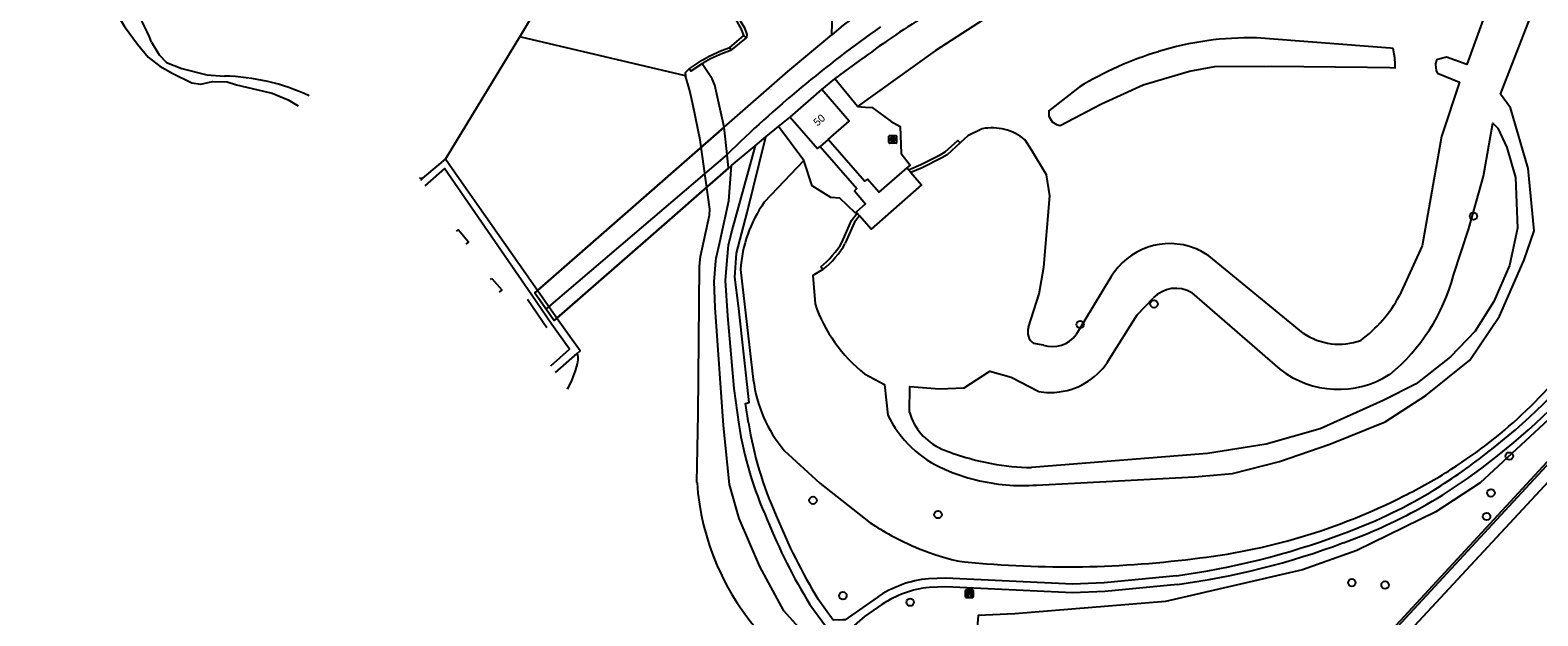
# Model space of a CAD drawing. Extents: x 155640 to 156810, y 382822 to 384046.
# Drawn here: x 156042.4 to 156240.5, y 383326 to 383402.9 of the extents above; entities that cross this region are included whole.
import ezdxf

# ---------------------------------------------------------------- set-up
doc = ezdxf.new("R2010")
doc.units = 0
for name, color, linetype in [('IMGEO_Bank', 7, 'Continuous'), ('IMGEO_Boom', 7, 'Continuous'), ('IMGEO_Dek', 7, 'Continuous'), ('IMGEO_Fietspad_gesloten', 7, 'Continuous'), ('IMGEO_Gemaal', 7, 'Continuous'), ('IMGEO_Groenvoorziening', 7, 'Continuous'), ('IMGEO_Haag', 7, 'Continuous'), ('IMGEO_Hek', 7, 'Continuous'), ('IMGEO_Kademuur', 7, 'Continuous'), ('IMGEO_Lijnafwatering', 7, 'Continuous'), ('IMGEO_Loofbos', 7, 'Continuous'), ('IMGEO_Meer_plas_ven_vijver', 7, 'Continuous'), ('IMGEO_Muur', 7, 'Continuous'), ('IMGEO_Pand', 7, 'Continuous'), ('IMGEO_Pand_nummerreeks', 7, 'Continuous'), ('IMGEO_Rijbaan_lokaal_gesloten', 7, 'Continuous'), ('IMGEO_Rioolput', 7, 'Continuous'), ('IMGEO_Terreindeel_halfverhard', 7, 'Continuous'), ('IMGEO_Voetpad_gesloten', 7, 'Continuous'), ('IMGEO_Voetpad_halfverhard', 7, 'Continuous'), ('IMGEO_Waterloop', 7, 'Continuous')]:
    doc.layers.add(name, color=color, linetype=linetype)

msp = doc.modelspace()

# ---------------------------------------------------------------- linework, layer by layer
at = {"layer": 'IMGEO_Bank'}
for p, q in [((156165.29, 383328.46), (156165.29, 383329.3)), ((156165.29, 383329.3), (156165.29, 383328.46)), ((156165.36, 383329.39), (156166.21, 383329.39)), ((156166.21, 383329.39), (156165.36, 383329.39)), ((156166.22, 383328.39), (156165.37, 383328.39)), ((156165.37, 383328.39), (156166.22, 383328.39)), ((156165.99, 383328.79), (156165.59, 383328.79)), ((156165.6, 383328.89), (156165.6, 383329)), ((156165.64, 383329), (156165.64, 383328.89)), ((156165.93, 383329.01), (156165.65, 383329.01)), ((156165.65, 383328.89), (156165.93, 383328.89)), ((156165.94, 383328.89), (156165.94, 383329)), ((156165.98, 383329), (156165.98, 383328.89)), ((156166.29, 383329.31), (156166.29, 383328.47)), ((156166.29, 383328.47), (156166.29, 383329.31))]:
    msp.add_line(p, q, dxfattribs=at)
for points in [[(156165.54, 383328.79), (156165.39, 383328.79), (156165.51, 383328.89), (156165.59, 383328.89)], [(156165.59, 383329.01), (156165.51, 383329.01), (156165.51, 383329.17), (156166.07, 383329.17), (156166.07, 383329.01), (156165.99, 383329.01)], [(156165.59, 383328.78), (156165.59, 383328.57), (156165.54, 383328.57), (156165.54, 383328.78)], [(156165.99, 383328.89), (156166.07, 383328.89), (156166.18, 383328.79), (156166.04, 383328.79)], [(156166.04, 383328.78), (156166.04, 383328.57), (156165.99, 383328.57), (156165.99, 383328.78)]]:
    msp.add_lwpolyline(points, dxfattribs=at)
for centre, radius, start, end in [((156165.37, 383329.31), 0.0779, 92.4484, 184.2845), ((156165.37, 383329.31), 0.0779, 92.4484, 184.2845), ((156165.37, 383328.47), 0.0779, 182.4484, 274.2845), ((156165.37, 383328.47), 0.0779, 182.4484, 274.2845), ((156165.54, 383328.78), 0.00671, 2.8957, 87.1043), ((156165.59, 383329), 0.00671, 2.8957, 87.1043), ((156165.59, 383328.89), 0.00671, 272.8957, 357.1043), ((156165.59, 383328.78), 0.00671, 92.8957, 177.1043), ((156165.65, 383329), 0.00671, 92.8957, 177.1043), ((156165.65, 383328.89), 0.00671, 182.8957, 267.1043), ((156165.93, 383329), 0.00671, 2.8957, 87.1043), ((156165.93, 383328.89), 0.00671, 272.8957, 357.1043), ((156165.99, 383329), 0.00671, 92.8957, 177.1043), ((156165.99, 383328.89), 0.00671, 182.8957, 267.1043), ((156165.99, 383328.78), 0.00671, 2.8957, 87.1043), ((156166.04, 383328.78), 0.00671, 92.8957, 177.1043), ((156166.21, 383329.31), 0.0779, 2.4484, 94.2845), ((156166.21, 383329.31), 0.0779, 2.4484, 94.2845), ((156166.21, 383328.47), 0.0779, 272.4484, 4.2845), ((156166.21, 383328.47), 0.0779, 272.4484, 4.2845)]:
    msp.add_arc(centre, radius, start, end, dxfattribs=at)
at = {"layer": 'IMGEO_Boom'}
for centre in [(156232.01, 383378.46), (156190.05, 383366.93), (156180.35, 383364.23), (156236.72, 383346.96), (156145.25, 383341.15), (156234.31, 383342.12), (156161.67, 383339.28), (156233.74, 383339.02), (156216.04, 383330.34), (156220.4, 383330.03), (156149.18, 383328.63), (156158.02, 383327.77)]:
    msp.add_circle(centre, 0.489, dxfattribs=at)
at = {"layer": 'IMGEO_Dek'}
msp.add_lwpolyline([(156134.16, 383384.76), (156133.97, 383386.57), (156133.6, 383390.13), (156118.82, 383377.21), (156109.06, 383368.68), (156108.72, 383368.39), (156111.25, 383364.74), (156123.58, 383375.52)], close=True, dxfattribs=at)
at = {"layer": 'IMGEO_Fietspad_gesloten'}
for points in [[(156150.23, 383404.29), (156149.2, 383403.52), (156147.71, 383402.28)], [(156133.6, 383390.13), (156141.94, 383397.47), (156147.71, 383402.28)], [(156133.97, 383386.57), (156133.6, 383390.13), (156118.82, 383377.21), (156109.06, 383368.68), (156108.72, 383368.39), (156110.18, 383366.29)], [(156133.97, 383386.57), (156133.6, 383390.13)], [(156133.97, 383386.57), (156110.18, 383366.29)]]:
    msp.add_lwpolyline(points, dxfattribs=at)
msp.add_arc((156250.07, 383267.46), 166.33, 125.2347, 134.2683, dxfattribs=at)
at = {"layer": 'IMGEO_Gemaal'}
for points in [[(156146.17, 383387.61), (156151, 383382.09), (156150.68, 383381.79), (156152.14, 383380.07), (156150.93, 383378.99)], [(156157.57, 383384.79), (156153.89, 383381.6), (156152.39, 383383.33), (156152.03, 383383.04), (156147.24, 383388.53)], [(156158.1, 383384.19), (156159.51, 383382.59), (156152.89, 383376.75), (156151.37, 383378.49)], [(156157.79, 383384.54), (156157.57, 383384.79)], [(156150.93, 383378.99), (156151.07, 383378.83)]]:
    msp.add_lwpolyline(points, dxfattribs=at)
at = {"layer": 'IMGEO_Groenvoorziening'}
for points in [[(156220.21, 383413.56), (156208.37, 383415.13), (156193.51, 383414.01), (156185.08, 383411.88), (156169.11, 383405.2), (156161.31, 383400.14), (156151.11, 383392.84)], [(156049.38, 383411.45), (156049.77, 383410.94), (156050.89, 383409.54), (156052.4, 383407.41), (156054.82, 383403.34), (156056.52, 383401.03), (156057.89, 383399.33), (156059.44, 383398.17), (156061.14, 383397.18), (156063.64, 383395.96), (156064.83, 383395.8), (156066.37, 383396.14), (156068.27, 383396.1), (156069.52, 383395.72), (156072.3, 383395.04), (156074.18, 383394.59), (156076.3, 383393.73), (156077.61, 383392.95)], [(156133.6, 383390.13), (156132.36, 383395.64), (156132, 383396.49), (156130.78, 383398.32), (156130.72, 383398.49)], [(156151.11, 383392.84), (156148.1, 383396.47)], [(156144.04, 383385.78), (156140.7, 383390.21)], [(156144.04, 383385.78), (156138.85, 383380.29)], [(156158.97, 383299.53), (156158.12, 383305.72), (156154.76, 383312), (156145.77, 383321.85), (156141.4, 383326.64), (156138.25, 383332.47), (156135.54, 383338.76), (156134.29, 383343.24), (156133.47, 383350.98), (156132.4, 383366.47), (156132.25, 383369.83), (156132.5, 383372.59), (156132.53, 383372.94), (156133, 383375.06), (156134.21, 383380.49), (156134.56, 383385.1)], [(156135.73, 383371.45), (156137.41, 383357.01)], [(156247.6, 383349.79), (156224.23, 383324.63)], [(156141.46, 383347.7), (156146.14, 383343.41), (156152.77, 383338.21)]]:
    msp.add_lwpolyline(points, dxfattribs=at)
for centre, radius, start, end in [((156153.04, 383370.31), 17.35, 144.9075, 176.2504), ((156194.92, 383399.02), 63.73, 302.4386, 325.059), ((156155.07, 383359.16), 17.79, 186.943, 220.0843), ((156195.43, 383397.91), 62.52, 296.0194, 302.5827), ((156186.49, 383413.22), 80.21, 276.1958, 296.9624), ((156172.46, 383367.49), 35.28, 236.083, 246.483), ((156172.49, 383367.56), 35.35, 246.4901, 256.3906), ((156178.48, 383464.15), 131.73, 263.7643, 277.2713)]:
    msp.add_arc(centre, radius, start, end, dxfattribs=at)
at = {"layer": 'IMGEO_Haag'}
for points in [[(156221.5, 383323.96), (156251.39, 383356.23)], [(156248.62, 383353.69), (156221.29, 383324.16), (156221.5, 383323.96)]]:
    msp.add_lwpolyline(points, dxfattribs=at)
at = {"layer": 'IMGEO_Hek'}
for points in [[(156118.82, 383377.21), (156133.6, 383390.13)], [(156134.16, 383384.76), (156123.58, 383375.52)], [(156109.06, 383368.68), (156118.82, 383377.21)], [(156123.58, 383375.52), (156111.25, 383364.74)], [(156108.72, 383368.39), (156109.06, 383368.68)], [(156224.23, 383324.63), (156247.6, 383349.79)]]:
    msp.add_lwpolyline(points, dxfattribs=at)
at = {"layer": 'IMGEO_Kademuur'}
for points in [[(156136.18, 383402.16), (156135.87, 383403), (156135.09, 383404.3), (156134.45, 383405.04), (156133.74, 383405.8), (156132.68, 383406.67), (156131.65, 383407.53), (156130.44, 383408.47), (156129.17, 383409.25), (156127.67, 383409.91), (156125.97, 383410.51), (156124.86, 383411.06), (156123.68, 383411.64), (156122.76, 383412.09), (156121.69, 383412.85)], [(156134.05, 383406.06), (156134.74, 383405.31), (156135.41, 383404.53), (156136.23, 383403.17), (156136.55, 383402.3), (156136.52, 383401.86)], [(156129, 383397.82), (156130.67, 383398.93), (156131.59, 383399.48), (156133.23, 383400.19), (156134.32, 383400.59)], [(156134.46, 383400.22), (156133.38, 383399.81), (156131.77, 383399.12), (156130.88, 383398.6), (156130.72, 383398.49)], [(156130.72, 383398.49), (156129.22, 383397.48), (156129, 383397.82)]]:
    msp.add_lwpolyline(points, dxfattribs=at)
at = {"layer": 'IMGEO_Lijnafwatering'}
msp.add_lwpolyline([(156107.73, 383367.54), (156110.27, 383363.84)], dxfattribs=at)
at = {"layer": 'IMGEO_Loofbos'}
msp.add_lwpolyline([(156247.72, 383357.2), (156232.9, 383343.44), (156227.05, 383339.62), (156216.67, 383334.58), (156209.55, 383332.04), (156191.54, 383327.89), (156171.75, 383326.24), (156166.93, 383326.02), (156165.8, 383312.12), (156170.26, 383297.35), (156172.98, 383289.47), (156173.05, 383289.27), (156175.83, 383284.03), (156175.34, 383282.18), (156181.24, 383276.16), (156184.1, 383272.27), (156188.18, 383271.12), (156190.33, 383268.72), (156196.74, 383263.77), (156194.3, 383261.15), (156197.14, 383258.02), (156201.28, 383254.76), (156204.42, 383253.88), (156208.17, 383256.03)], dxfattribs=at)
at = {"layer": 'IMGEO_Meer_plas_ven_vijver'}
for points in [[(156106.72, 383402.02), (156114.8, 383415.47)], [(156058.34, 383401.31), (156059.37, 383399.63), (156060.31, 383398.65), (156062.32, 383397.83), (156065.63, 383397.01), (156067.93, 383396.84)], [(156096.95, 383385.92), (156106.72, 383402.02)], [(156128.5, 383396.88), (156106.72, 383402.02)], [(156129, 383397.82), (156128.74, 383397.55), (156128.46, 383397.26), (156128.5, 383396.88)], [(156130.01, 383343.5), (156130.18, 383352.47), (156130.34, 383371.89), (156130.46, 383373.16), (156131.67, 383378.6), (156131.71, 383379.38), (156130.42, 383388.48), (156129.5, 383392.94), (156129.07, 383394.91), (156128.5, 383396.88)], [(156093.54, 383383.47), (156094.01, 383383.43)], [(156114.26, 383360.43), (156114.35, 383360.04), (156114.34, 383359.6), (156114.26, 383359.07), (156114.02, 383358.14), (156113.48, 383356.73), (156112.96, 383355.73)]]:
    msp.add_lwpolyline(points, dxfattribs=at)
for centre, radius, start, end in [((156030.75, 383390.28), 29.72, 21.7875, 66.9009), ((156067.31, 383368.96), 27.89, 65.0916, 88.7313), ((156162.9, 383345.69), 32.96, 183.8144, 223.1671)]:
    msp.add_arc(centre, radius, start, end, dxfattribs=at)
at = {"layer": 'IMGEO_Muur'}
for points in [[(156134.32, 383400.59), (156136.18, 383402.16)], [(156134.46, 383400.22), (156136.52, 383401.86)], [(156136.52, 383401.86), (156136.18, 383402.16)], [(156134.32, 383400.59), (156134.46, 383400.22)], [(156157.79, 383384.54), (156159.42, 383385.23), (156161.95, 383386.49), (156162.59, 383386.89), (156164.26, 383388.41), (156164.57, 383388.08)], [(156164.57, 383388.08), (156162.86, 383386.53), (156162.17, 383386.1), (156159.61, 383384.82), (156158.1, 383384.19)], [(156094.01, 383383.43), (156096.16, 383385.25), (156096.95, 383385.92)], [(156114.26, 383360.43), (156114.67, 383360.78), (156113.3, 383362.68), (156111.75, 383364.82), (156109.06, 383368.68), (156097.84, 383384.66), (156096.95, 383385.92)], [(156093.73, 383383.19), (156094.01, 383383.43)], [(156110.81, 383358.79), (156113.28, 383360.98), (156110.93, 383364.25), (156108.33, 383368.1), (156096.82, 383384.7), (156094.25, 383382.46)], [(156158.1, 383384.19), (156157.79, 383384.54)], [(156149.07, 383375.1), (156150.31, 383377.88), (156151.07, 383378.83)], [(156151.37, 383378.49), (156150.7, 383377.65), (156149.48, 383374.9)], [(156151.07, 383378.83), (156151.37, 383378.49)], [(156146.54, 383371.46), (156146.26, 383371.81)], [(156111.41, 383357.93), (156114.26, 383360.43)]]:
    msp.add_lwpolyline(points, dxfattribs=at)
for centre, radius, start, end in [((156139.2, 383380.7), 11.36, 308.4635, 330.4373), ((156139.23, 383380.67), 11.77, 308.4256, 330.5808)]:
    msp.add_arc(centre, radius, start, end, dxfattribs=at)
at = {"layer": 'IMGEO_Pand'}
for points in [[(156142.25, 383391.47), (156146.42, 383395.08)], [(156147.24, 383388.53), (156150.02, 383390.93), (156146.42, 383395.08)], [(156142.25, 383391.47), (156145.85, 383387.33), (156146.17, 383387.61)], [(156147.24, 383388.53), (156146.17, 383387.61)]]:
    msp.add_lwpolyline(points, dxfattribs=at)
at = {"layer": 'IMGEO_Rijbaan_lokaal_gesloten'}
for points in [[(156098.43, 383376.48), (156098.67, 383376.67), (156099.98, 383375.08), (156099.62, 383374.78)], [(156102.88, 383370.12), (156103.05, 383370.26)], [(156103.05, 383370.26), (156104.35, 383368.77), (156104.02, 383368.49)]]:
    msp.add_lwpolyline(points, dxfattribs=at)
at = {"layer": 'IMGEO_Rioolput'}
for p, q in [((156155.23, 383388.11), (156155.23, 383388.96)), ((156155.31, 383389.03), (156156.16, 383389.03)), ((156156.16, 383388.03), (156155.31, 383388.03)), ((156155.72, 383388.81), (156155.75, 383388.81)), ((156155.74, 383388.25), (156155.72, 383388.25)), ((156156.24, 383388.96), (156156.24, 383388.11))]:
    msp.add_line(p, q, dxfattribs=at)
for points in [[(156155.23, 383388.11), (156155.23, 383388.96)], [(156155.31, 383389.03), (156156.16, 383389.03)], [(156156.16, 383388.03), (156155.31, 383388.03)], [(156155.82, 383388.73), (156155.57, 383388.73), (156155.57, 383388.33)], [(156155.57, 383388.33), (156155.7, 383388.33), (156155.7, 383388.5), (156155.71, 383388.5)], [(156155.75, 383388.65), (156155.7, 383388.65), (156155.7, 383388.57)], [(156155.7, 383388.57), (156155.75, 383388.57)], [(156155.75, 383388.47), (156155.82, 383388.33), (156155.96, 383388.33), (156155.9, 383388.46)], [(156156.24, 383388.96), (156156.24, 383388.11)]]:
    msp.add_lwpolyline(points, dxfattribs=at)
for centre, radius, start, end in [((156155.31, 383388.96), 0.0765, 91.552, 178.448), ((156155.31, 383388.96), 0.0765, 91.552, 178.448), ((156155.31, 383388.11), 0.0765, 181.552, 268.448), ((156155.31, 383388.11), 0.0765, 181.552, 268.448), ((156155.7, 383388.44), 0.0533, 26.0293, 88.6989), ((156155.75, 383388.56), 0.0964, 77.0061, 93.1865), ((156155.73, 383388.76), 0.19, 274.7715, 282.9687), ((156155.77, 383388.61), 0.0378, 276.6634, 79.6772), ((156155.82, 383388.62), 0.109, 350.3612, 89.416), ((156155.82, 383388.62), 0.112, 277.5842, 350.9817), ((156155.8, 383388.41), 0.108, 29.5134, 73.7905), ((156156.16, 383388.96), 0.0765, 1.552, 88.448), ((156156.16, 383388.96), 0.0765, 1.552, 88.448), ((156156.16, 383388.11), 0.0765, 271.552, 358.448), ((156156.16, 383388.11), 0.0765, 271.552, 358.448)]:
    msp.add_arc(centre, radius, start, end, dxfattribs=at)
for centre, major_axis, ratio, start_param, end_param in [((156155.72, 383388.53), (-0.387, 0.002), 0.722429, 4.712389, 7.853982), ((156155.75, 383388.53), (-0.39, 0.002), 0.717154, 1.570796, 4.712389)]:
    msp.add_ellipse(centre, major_axis=major_axis, ratio=ratio, start_param=start_param, end_param=end_param, dxfattribs=at)
at = {"layer": 'IMGEO_Terreindeel_halfverhard'}
for points in [[(156151.11, 383392.84), (156152.15, 383392.77), (156153.04, 383392.71), (156155.52, 383390.87), (156156.69, 383390.22), (156156.83, 383386.67), (156158.02, 383385.17), (156157.57, 383384.79)], [(156150.93, 383378.99), (156150.79, 383378.88), (156148.76, 383380.82), (156147.57, 383380.9), (156145.14, 383382.42), (156144.04, 383385.78)]]:
    msp.add_lwpolyline(points, dxfattribs=at)
at = {"layer": 'IMGEO_Voetpad_gesloten'}
for points in [[(156148.1, 383396.47), (156151.87, 383399.23)], [(156146.42, 383395.08), (156148.1, 383396.47)], [(156140.7, 383390.21), (156142.25, 383391.47)], [(156139.07, 383388.85), (156140.7, 383390.21)], [(156134.56, 383385.1), (156137.65, 383387.68)], [(156137.65, 383387.68), (156139.07, 383388.85)], [(156110.18, 383366.29), (156111.25, 383364.74), (156123.58, 383375.52), (156134.16, 383384.76), (156133.97, 383386.57)], [(156134.56, 383385.1), (156134.16, 383384.76), (156133.97, 383386.57)]]:
    msp.add_lwpolyline(points, dxfattribs=at)
msp.add_arc((156209.46, 383323.03), 95.51, 120.8641, 127.0806, dxfattribs=at)
at = {"layer": 'IMGEO_Voetpad_halfverhard'}
for points in [[(156147.71, 383402.28), (156147.8, 383405.44), (156146.24, 383407.62)], [(156137.65, 383387.68), (156134.71, 383377.04), (156134.11, 383374.66), (156133.91, 383372.67), (156133.7, 383370.02), (156134.01, 383365.35), (156134.83, 383355.83), (156135.52, 383351.12)], [(156136.78, 383351.34), (156136.37, 383353.87), (156136.86, 383353.98), (156135.45, 383366.67), (156135, 383370.43), (156135.22, 383373.59), (156136.58, 383378.95), (156139.07, 383388.85)], [(156192.99, 383331.25), (156183.51, 383330.32), (156179.34, 383330.16), (156162.72, 383330.94), (156160.43, 383330.86)], [(156193.13, 383330.11), (156183.59, 383329.17), (156179.34, 383329.02), (156168.2, 383329.54), (156162.71, 383329.79), (156160.5, 383329.71)], [(156147.92, 383325.44), (156145.89, 383328.2)], [(156153.67, 383328.41), (156149.47, 383325.45), (156149.18, 383325.45), (156147.92, 383325.44)], [(156144.83, 383327.48), (156146.89, 383324.66)], [(156154.31, 383327.46), (156152.02, 383325.89), (156150.36, 383324.44), (156150.11, 383322.93)]]:
    msp.add_lwpolyline(points, dxfattribs=at)
for centre, radius, start, end in [((156185.71, 383410.15), 79.07, 307.3408, 321.7392), ((156185.73, 383410.13), 80.19, 307.3491, 321.7478), ((156182.75, 383358.37), 47.79, 188.7208, 204.4272), ((156182.64, 383358.33), 46.38, 188.6639, 204.4765), ((156192.76, 383398.51), 66.7, 297.7734, 308.6073), ((156192.93, 383398.28), 65.26, 300.7818, 308.6328), ((156192.64, 383398.64), 65.73, 289.4548, 300.8314), ((156208.62, 383366.47), 74.77, 201.8858, 211.4337), ((156208.71, 383366.52), 73.58, 201.8699, 211.3861), ((156192.81, 383398.23), 66.43, 289.4433, 297.8444), ((156179.8, 383429.17), 98.81, 277.6723, 290.5779), ((156179.82, 383429.12), 99.9, 277.6581, 290.5763), ((156161.77, 383316.59), 14.33, 95.3842, 124.4541), ((156161.77, 383316.59), 13.18, 95.5253, 124.4647)]:
    msp.add_arc(centre, radius, start, end, dxfattribs=at)
at = {"layer": 'IMGEO_Waterloop'}
for points in [[(156242.99, 383422.51), (156238.82, 383418.36), (156235.99, 383411.8), (156231.16, 383398.36), (156228.45, 383399.31), (156227.17, 383398.98), (156227.04, 383398.39), (156227.12, 383397.52), (156227.3, 383397.22), (156230.18, 383396.06), (156227.83, 383388.92), (156225.28, 383374.58), (156222.3, 383368.02)], [(156174.61, 383343.16), (156195.37, 383344.22), (156200.37, 383344.68), (156206.55, 383346.26), (156213.13, 383348.53), (156220.42, 383351.46), (156225.74, 383354.93), (156231.53, 383359.57), (156235.44, 383365.33), (156238.69, 383372.71), (156239.97, 383376.54), (156239.22, 383384.7), (156236.9, 383392.66), (156235.55, 383394.46), (156241.39, 383409.48), (156243.02, 383412.9)], [(156221.46, 383400.46), (156221.1, 383400.51), (156220.49, 383400.56), (156203.5, 383401.86)], [(156180.23, 383395.4), (156176.22, 383392.27), (156176.21, 383391.6), (156176.68, 383390.83), (156177.24, 383390.5), (156177.71, 383390.37), (156183.16, 383393.22), (156188.63, 383395.7), (156194.69, 383397.49), (156198.03, 383398.09), (156205.51, 383398.15), (156218.08, 383398.02), (156221.03, 383397.99), (156221.73, 383397.92), (156221.72, 383398.39), (156221.67, 383399.23), (156221.46, 383400.46)], [(156167.47, 383389.93), (156165.61, 383389.01), (156164.57, 383388.08)], [(156229.4, 383370.7), (156231.4, 383376.84), (156233.35, 383383.71), (156234.56, 383390.66), (156235.21, 383390.01), (156236.38, 383387.45), (156237.52, 383383.54), (156237.78, 383376.88), (156236.73, 383371.97), (156234.68, 383367.25), (156232.25, 383363.38), (156229.01, 383360.01), (156224.47, 383356.46), (156220.16, 383354.24), (156211.86, 383350.52), (156204.77, 383348.54), (156197.09, 383347.3), (156173.96, 383345.45)], [(156173.58, 383363.88), (156174.97, 383368.24), (156175.59, 383371.76), (156176.38, 383381.12), (156175.93, 383383.9), (156173.98, 383387.06), (156173.08, 383388.5)], [(156209.65, 383363.1), (156197.25, 383373.25)], [(156146.54, 383371.46), (156145.21, 383370.68), (156145.52, 383366.94)], [(156184.37, 383370.43), (156179.83, 383362.92)], [(156184.21, 383359.73), (156187.84, 383365.51), (156189.93, 383367.71)], [(156195.03, 383368.41), (156206.56, 383358.38)], [(156175.51, 383361.52), (156174.28, 383361.74)], [(156152.03, 383357.74), (156154.63, 383356.36), (156155.08, 383352.35)], [(156157.92, 383352.7), (156157.99, 383356.1), (156161.87, 383355.78), (156165.09, 383355.94), (156168.46, 383358.1), (156171.3, 383357.3), (156174.9, 383355.43)]]:
    msp.add_lwpolyline(points, dxfattribs=at)
for centre, radius, start, end in [((156202.58, 383361.78), 40.09, 88.6877, 107.3191), ((156203.25, 383357.81), 44.08, 106.6143, 121.4891), ((156168.75, 383383.2), 6.85, 50.6793, 100.7397), ((156192.13, 383365.83), 9.02, 68.2737, 149.3383), ((156192.09, 383365.76), 9.09, 55.4276, 68.1974), ((156204.9, 383377.29), 25.38, 309.4452, 344.9415), ((156192.92, 383364.82), 4.16, 59.5584, 135.9178), ((156207, 383376.14), 17.31, 306.0888, 332.0372), ((156164.57, 383373.53), 20.16, 199.0793, 231.5435), ((156175.21, 383363.23), 1.76, 158.3184, 238.15), ((156176.72, 383365.15), 3.82, 251.5832, 324.3915), ((156214.36, 383370.01), 8.36, 235.7095, 289.8949), ((156176.42, 383364.37), 9.07, 277.5543, 329.2265), ((156214.28, 383368.28), 12.55, 232.0759, 302.5001), ((156176.42, 383364.35), 9.04, 260.2885, 277.5592), ((156168.2, 383358.63), 14.54, 205.5917, 247.1195), ((156165.27, 383354.91), 7.68, 196.6887, 245.1877), ((156174.7, 383378.78), 33.34, 247.7037, 259.6403), ((156174.72, 383378.96), 33.52, 259.6588, 268.7109), ((156172.72, 383368.37), 25.27, 246.2559, 256.0878), ((156172.73, 383368.41), 25.32, 256.0865, 274.2565)]:
    msp.add_arc(centre, radius, start, end, dxfattribs=at)

# ---------------------------------------------------------------- texts
at = {"layer": 'IMGEO_Pand_nummerreeks'}
msp.add_text('50', height=1, rotation=41.0696, dxfattribs=at).set_placement((156145.83, 383390.21))

doc.saveas('drawing.dxf')
